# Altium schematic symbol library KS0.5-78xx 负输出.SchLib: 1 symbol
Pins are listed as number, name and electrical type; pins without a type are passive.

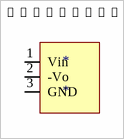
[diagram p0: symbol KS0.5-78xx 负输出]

## KS0.5-78xx 负输出
designator *
footprint Model Name (Footprint not found)
pins: 1 Vin, 2 -Vo, 3 GND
